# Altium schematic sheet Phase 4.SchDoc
size Tabloid; SheetNumber: 6; SheetTotal: 7
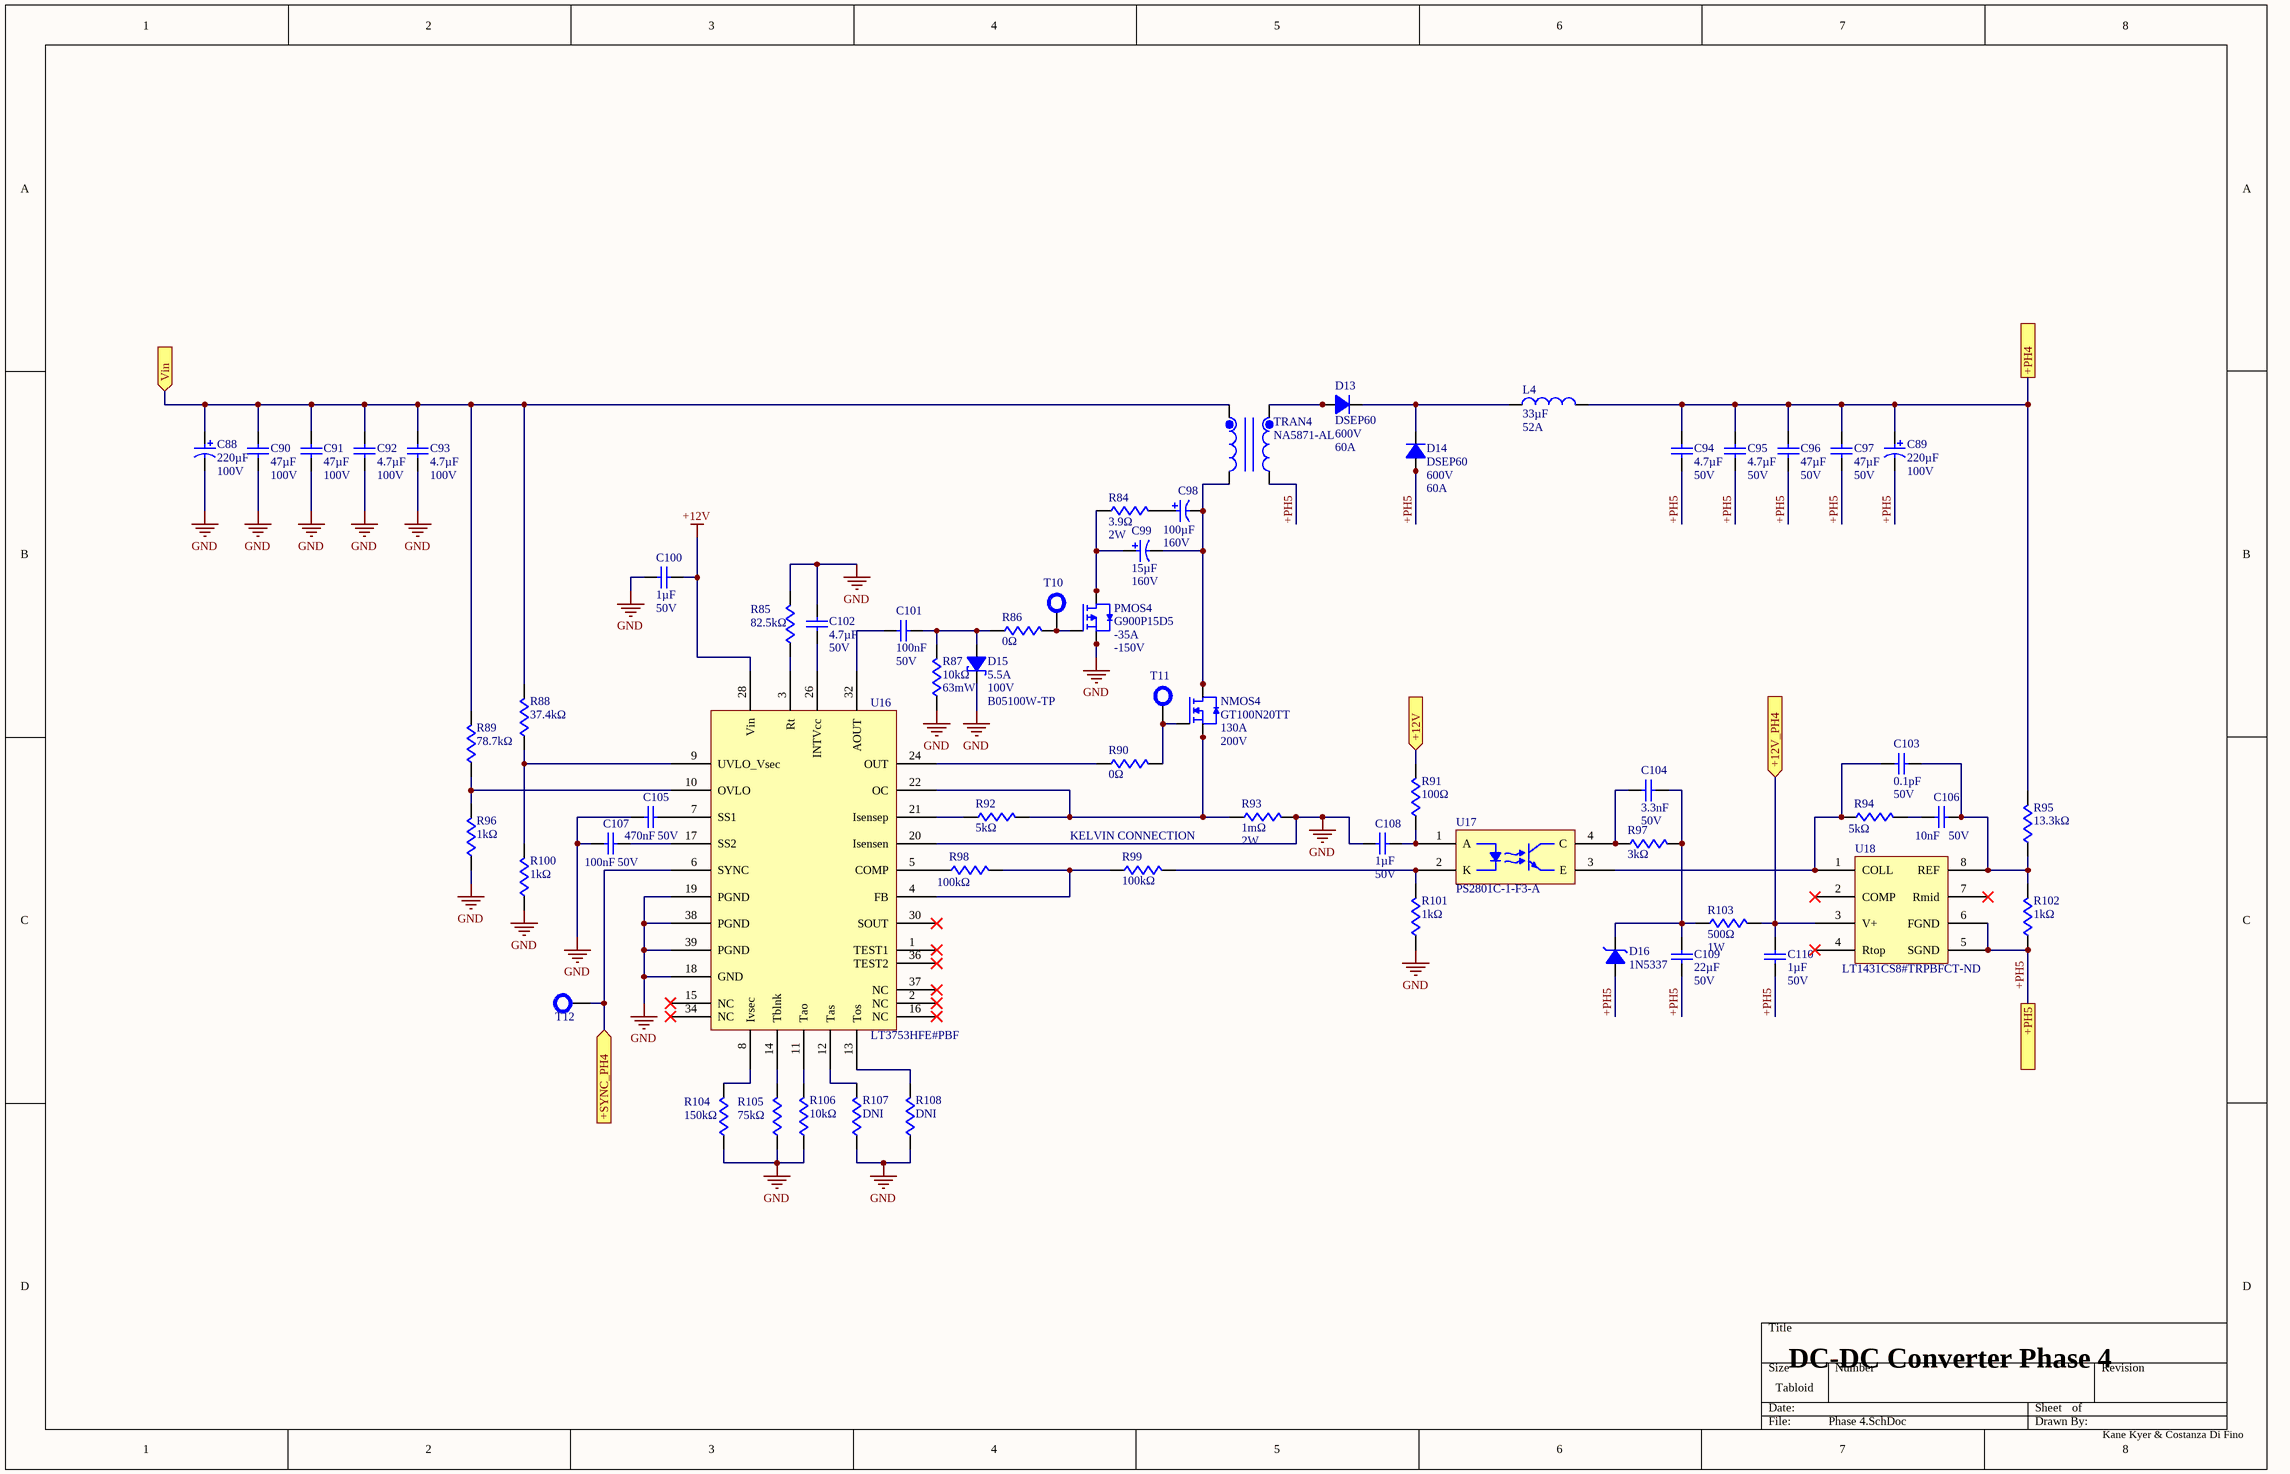
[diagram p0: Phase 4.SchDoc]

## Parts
C88  value 220µF  Voltage Rating: 100V  [C_AEC]  (hidden comment: AFK227M2AR44T-F)
C89  value 220µF  Voltage Rating: 100V  [C_AEC]  (hidden comment: AFK227M2AR44T-F)
C90  value 47µF  Voltage Rating: 100V  [C_CAA573]  (hidden comment: CAA573X7S2A476M640LH)
C91  value 47µF  Voltage Rating: 100V  [C_CAA573]  (hidden comment: CAA573X7S2A476M640LH)
C92  value 4.7µF  Voltage Rating (DC): 100V  [C_1210]  (hidden comment: GMC32X7S475K100NT)
C93  value 4.7µF  Voltage Rating (DC): 100V  [C_1210]  (hidden comment: GMC32X7S475K100NT)
C94  value 4.7µF  Voltage Rating (DC): 50V  [C_1206]  (hidden comment: GMC31X7R475K50NT)
C95  value 4.7µF  Voltage Rating (DC): 50V  [C_1206]  (hidden comment: GMC31X7R475K50NT)
C96  value 47µF  Voltage Rating (DC): 50V  [C_CKG57N]  (hidden comment: CKG57NX7R1H476M500JJ)
C97  value 47µF  Voltage Rating (DC): 50V  [C_CKG57N]  (hidden comment: CKG57NX7R1H476M500JJ)
C98  value 100µF  Voltage Rating (DC): 160V  [UUJ2C101MNJ1MS]  (hidden comment: UUJ2C101MNJ1MS)
C99  value 15µF  Voltage: 160V  [ULT2C150MNL1GS]  (hidden comment: ULT2C150MNL1GS)
C100  value 1µF  Voltage: 50V  [C_0805]  (hidden comment: CL21B105KBFNNNE)
C101  value 100nF  Voltage Rating: 50V  [C_0603]  (hidden comment: C0603C104K5RACTU)
C102  value 4.7µF  Voltage Rating (DC): 50V  [C_1206]  (hidden comment: GMC31X7R475K50NT)
C103  value 0.1pF  Voltage Rating: 50V  [C_0402]  (hidden comment: GJM1555C1HR10WB01D)
C104  value 3.3nF  Voltage Rating: 50V  [C_0603]  (hidden comment: GCM1885C1H332FA16D)
C105  value 470nF  Voltage Rating: 50V  [C_0402]  (hidden comment: GRM155R61H474KE11D)
C106  value 10nF  Voltage Rating: 50V  [C_0603]  (hidden comment: C0603C103K5RACTU)
C107  value 100nF  Voltage Rating: 50V  [C_0603]  (hidden comment: C0603C104K5RACTU)
C108  value 1µF  Voltage: 50V  [C_0805]  (hidden comment: CL21B105KBFNNNE)
C109  value 22µF  Voltage Rating (DC): 50V  [C_2220]  (hidden comment: GMC55X7R226M50NT)
C110  value 1µF  Voltage: 50V  [C_0805]  (hidden comment: CL21B105KBFNNNE)
D13  DSEP60  Vr: 600V  Io: 60A  [D_DSEP60]
D14  DSEP60  Vr: 600V  Io: 60A  [D_DSEP60]
D15  Max Forward Surge Current (Ifsm): 5.5A  Min Breakdown Voltage: 100V  [D_B05100W]  (hidden comment: B05100W-TP)
D16  Supplier Part Number: 1N5337  [D_1N5337]  (hidden comment: 1N5337BRLG)
L4  value 33µF  Irms: 52A  [CPEX4141L-330MC]  (hidden comment: CPEX4141L-330MC)
NMOS4  Id: 130A  Vds: 200V  [GT100N20TT]  (hidden comment: GT100N20TT)
PMOS4  Id: -35A  Vds: -150V  [G900P15]  (hidden comment: G900P15D5)
R84  value 3.9Ω  Power Rating: 2W  [R_SM2W]  (hidden comment: SMW23R9JT)
R85  value 82.5kΩ  [R_0805]  (hidden comment: RMCF0805FT82K5)
R86  value 0Ω  [R_0805]  (hidden comment: CRCW08050000Z0EA)
R87  value 10kΩ  Power Rating: 63mW  [R_0402]  (hidden comment: RM04F1002CT)
R88  value 37.4kΩ  [R_0603]  (hidden comment: RC0603FR-0737K4L)
R89  value 78.7kΩ  [R_0603]  (hidden comment: RC0603FR-0778K7L)
R90  value 0Ω  [R_0805]  (hidden comment: CRCW08050000Z0EA)
R91  value 100Ω  [R_0603]  (hidden comment: RC0603FR-07100RL)
R92  value 5kΩ  [R_0402]  (hidden comment: PNM0402E5001BST1)
R93  value 1mΩ  Power Rating: 2W  [R_2512]  (hidden comment: CRE2512-FZ-R001E-2)
R94  value 5kΩ  [R_0402]  (hidden comment: PNM0402E5001BST1)
R95  value 13.3kΩ  [R_0603]  (hidden comment: RMCF0603FT13K3)
R96  value 1kΩ  [R_0402]  (hidden comment: RM04F1001CT)
R97  value 3kΩ  [C_0402]  (hidden comment: AC0402FR-073KL)
R98  value 100kΩ  [R_0402]  (hidden comment: RM04F1003CT)
R99  value 100kΩ  [R_0402]  (hidden comment: RM04F1003CT)
R100  value 1kΩ  [R_0402]  (hidden comment: RM04F1001CT)
R101  value 1kΩ  [R_0402]  (hidden comment: RM04F1001CT)
R102  value 1kΩ  [R_0402]  (hidden comment: RM04F1001CT)
R103  value 500Ω  Power Rating: 1W  [R_WSC2515]  (hidden comment: WSC2515500R0FEB)
R104  value 150kΩ  [R_0603]  (hidden comment: RC0603FR-07150KL)
R105  value 75kΩ  [R_0603]  (hidden comment: AC0603FR-0775KL)
R106  value 10kΩ  [R_0402]  (hidden comment: RM04F1002CT)
R107  value DNI  [R_0805]  (hidden comment: CRCW08050000Z0EA)
R108  value DNI  [R_0805]  (hidden comment: CRCW08050000Z0EA)
T10  TEST  [TEST_POINT]  (value not drawn)
T11  TEST  [TEST_POINT]  (value not drawn)
T12  TEST  [TEST_POINT]  (value not drawn)
TRAN4  NA5871-AL  [NA5871-AL]
U16  LT3753HFE#PBF  [LT3753]
U17  PS2801C-1-F3-A  [PS2801C]
U18  Supplier Part Number: LT1431CS8#TRPBFCT-ND  [LT1431]  (hidden comment: LT1431CS8#TRPBF)

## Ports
+12V (in, see SHEET_MAP[4C], Externals[2A], Phase 1[4C], Phase 2[4C], Phase 3[4C], Phase 5[4B]), +12V_PH4 (in, see SHEET_MAP[4C], Externals[6B]), +PH4 (see SHEET_MAP[4C], Externals[6B], Phase 3[6C]), +PH5 (see SHEET_MAP[4C], Externals[6C], Phase 5[6B]), +SYNC_PH4 (in, see SHEET_MAP[4C], Externals[3C]), Vin (in, see SHEET_MAP[4C], Externals[1A], Phase 1[1B], Phase 2[1B], Phase 3[1B], Phase 5[1B])

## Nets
+12V: C100.2 U16.28(Vin)
GND: C88.2 C90.1 C91.1 C92.1 C93.1 C100.1 C102.1 C105.1 C107.1 C108.1 D15.1 PMOS4.1(S) PMOS4.2(S) PMOS4.3(S) R85.2 R87.1 R93.2 R96.1 R100.1 R101.1 R104.1 R105.1 R106.1 R107.1 R108.1 U16.18(GND) U16.19(PGND) U16.20(Isensen) U16.38(PGND) U16.39(PGND)
+12V: R91.2 ; port +12V  [a separate net that carries the same name]
+12V_PH4: C110.2 R103.2 U18.3(V+) ; port +12V_PH4
+PH4: C89.1 C94.2 C95.2 C96.2 C97.2 L4.2 R95.2 ; port +PH4
+PH5: C89.2 C94.1 C95.1 C96.1 C97.1 C109.1 C110.1 D14.1(A) D14.3(A) D16.2 R102.1 TRAN4.11 U18.5(SGND) U18.6(FGND) ; port +PH5
+SYNC_PH4: T12.1 U16.6(SYNC) ; port +SYNC_PH4
Vin: C88.1 C90.2 C91.2 C92.2 C93.2 R88.2 R89.2 TRAN4.1 ; port Vin
NetC98_1: C98.1 R84.2
NetC98_2: C98.2 C99.2 NMOS4.9(D) NMOS4.10(D) NMOS4.11(D) NMOS4.12(D) NMOS4.13(D) NMOS4.14(D) NMOS4.15(D) NMOS4.16(D) TRAN4.4
NetC99_1: C99.1 PMOS4.5(D) PMOS4.6(D) PMOS4.7(D) PMOS4.8(D) R84.1
NetC101_1: C101.1 U16.32(AOUT)
NetC101_2: C101.2 D15.2 R86.1 R87.2
NetC102_2: C102.2 U16.26(INTVcc)
NetC103_1: C103.1 R94.1 U17.3(E) U18.1(COLL)
NetC103_2: C103.2 C106.2 R95.1 R102.2 U18.8(REF)
NetC104_1: C104.1 R97.1 U17.4(C)
NetC104_2: C104.2 C109.2 D16.1 R97.2 R103.1
NetC105_2: C105.2 U16.7(SS1)
NetC106_1: C106.1 R94.2
NetC107_2: C107.2 U16.17(SS2)
NetC108_2: C108.2 R91.1 U17.1(A)
NetD13_1: D13.1(A) D13.3(A) TRAN4.6
NetD13_4: D13.4(C) D14.4(C) L4.1
NetNMOS4_1: NMOS4.1(S) NMOS4.2(S) NMOS4.3(S) NMOS4.4(S) NMOS4.5(S) NMOS4.6(S) NMOS4.7(S) R92.2 R93.1 U16.22(OC)
NetNMOS4_8: NMOS4.8(G) R90.2 T11.1
NetPMOS4_4: PMOS4.4(G) R86.2 T10.1
NetR85_1: R85.1 U16.3(Rt)
NetR88_1: R88.1 R100.2 U16.9(UVLO_Vsec)
NetR89_1: R89.1 R96.2 U16.10(OVLO)
NetR90_1: R90.1 U16.24(OUT)
NetR92_1: R92.1 U16.21(Isensep)
NetR98_1: R98.1 U16.5(COMP)
NetR98_2: R98.2 R99.1 U16.4(FB)
NetR99_2: R99.2 R101.2 U17.2(K)
NetR104_2: R104.2 U16.8(Ivsec)
NetR105_2: R105.2 U16.14(Tblnk)
NetR106_2: R106.2 U16.11(Tao)
NetR107_2: R107.2 U16.12(Tas)
NetR108_2: R108.2 U16.13(Tos)

Not connected (* = marked no-connect by the designer): U16 1(TEST1)* 2(NC)* 15(NC)* 16(NC)* 30(SOUT)* 34(NC)* 36(TEST2)* 37(NC)*; U18 2(COMP)* 4(Rtop)* 7(Rmid)*

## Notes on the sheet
- (near R99) KELVIN CONNECTION
- DC-DC Converter Phase 4
- Kane Kyer & Costanza Di Fino

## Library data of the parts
C88 C89 = AFK227M2AR44T-F: Radial Can - SMD ALUMINUM ELECTROLYTIC CAPACITOR AFK 100V 220muF ±20% 0.709Dia 18.00mm; Manufacturer: Cornell Dubilier; Dissipation Factor: 0.07%; ESR (Equivalent Series Resistance): 150mΩ; Leakage Current: 220µA; Life (Hours): 5000hours; Ripple Current: 687.75mA; Ripple Current (AC): 917mA
C90 C91 = CAA573X7S2A476M640LH: Multilayer Ceramic Chip Capacitors, Capacitance=47μF, LxWxT: 6.0x7.5x6.4mm; Manufacturer: TDK; Manufacturer Lifecycle Status: PRODUCTION; Tolerance: 20%
C92 C93 = GMC32X7S475K100NT: Ceramic Capacitor, Multilayer, Ceramic, 100V, 10% +Tol, 10% -Tol, X7S, 22% TC, 4.7uF, Surface Mount, 1210; Manufacturer: Cal-Chip Electronics
C94 C95 C102 = GMC31X7R475K50NT: Ceramic Capacitor, Multilayer, Ceramic, 50V, 10% +Tol, 10% -Tol, X7R, 15% TC, 4.7uF, Surface Mount, 1206; Manufacturer: Cal-Chip Electronics
C96 C97 = CKG57NX7R1H476M500JJ: Ceramic Capacitor, Multilayer, Ceramic, 50V, 20% +Tol, 20% -Tol, X7R, 15% TC, 47uF, Surface Mount, 2420; Manufacturer: TDK; Manufacturer Lifecycle Status: PRODUCTION
C98 = UUJ2C101MNJ1MS: Aluminum Electrolytic Capacitors 100 F 160 V Radial, SMD 5000 Hrs 105C; Manufacturer: Nichicon; Leakage Current: 740µA; Ripple Current: 380mA
C99 = ULT2C150MNL1GS: Radial Can - SMD ALUMINUM ELECTROLYTIC CAPACITOR ULT 160V 15muF ±20% 0.315Dia 8.00mm; Manufacturer: Nichicon; Leakage Current: 196µA; Life (Hours): 2000hours; Polarity: Polar; Ripple Current: 45mA
C100 C108 C110 = CL21B105KBFNNNE: 50V 1uF X7R ±10% 0805 Multilayer Ceramic Capacitors MLCC - SMD/SMT ROHS; Manufacturer: Samsung Electro-Mechanics
C101 C107 = C0603C104K5RACTU: 50V 100nF X7R ±10% 0603 Multilayer Ceramic Capacitors MLCC - SMD/SMT ROHS; Manufacturer: KEMET; Dissipation Factor: 2.5%; Temperature Coefficient: 30ppm/°C
C103 = GJM1555C1HR10WB01D: Multilayer Ceramic Capacitor, 0.1 pF, 50 V, ± 0.05pF, C0G (NP0), 0402 [1005 Metric]; Manufacturer: Murata; Manufacturer Lifecycle Status: IN PRODUCTION; Temperature Coefficient: 30ppm/°C
C104 = GCM1885C1H332FA16D: 50V 3.3nF C0G ±1% 0603 Multilayer Ceramic Capacitors MLCC - SMD/SMT ROHS; Manufacturer: Murata; Manufacturer Lifecycle Status: IN PRODUCTION; Temperature Coefficient: 30ppm/°C
C105 = GRM155R61H474KE11D: 50V 470nF X5R ±10% 0402 Multilayer Ceramic Capacitors MLCC - SMD/SMT ROHS; Manufacturer: Murata; Manufacturer Lifecycle Status: IN PRODUCTION
C106 = C0603C103K5RACTU: Capacitor, Multilayer, Ceramic, 50V, 10%, X7R, 15% Tc, 0.01Uf, Surface Mount, 0603; Manufacturer: KEMET; Dissipation Factor: 2.5%; Temperature Coefficient: 30ppm/°C
C109 = GMC55X7R226M50NT: Ceramic Capacitor, Multilayer, Ceramic, 50V, 20% +Tol, 20% -Tol, X7R, 15% TC, 22uF, Surface Mount, 2220; Manufacturer: Cal-Chip Electronics
D13 D14 = DSEP60-06AZ-TRL: Power Diode Discretes-FRED TO-; Manufacturer: IXYS
D15 = B05100W-TP: Rectifier Diode, Schottky, 1 Phase, 1 Element, 0.5A, 100V V(RRM), Silicon; Manufacturer: MCC; Forward Voltage: 850mV; Max Output current: 500mA; Number of Elements: 1; Peak Reverse Current: 1µA
D16 = 1N5337BRLG: Zener Diode Single 4.7V 5% 2Ohm 5000mW 2-Pin Case 017AA-01 T/R / DIODE ZENER 4.7V 5W AXIAL; Manufacturer: onsemi; Manufacturer Lifecycle Status: ACTIVE; Forward Voltage: 1.2V; Impedance: 2Ω; Max Reverse Leakage Current: 5µA; Number of Elements: 1; Polarity: Unidirectional; Test Current: 260mA
L4 = CPEX4141L-330MC: Fixed Ind 33UH 52A 1.88 Mohm Th; Manufacturer: Codaca
NMOS4 = GT100N20TT: Mosfet N-ch 200V 130A 280W Tolt; Manufacturer: GoFord
PMOS4 = G900P15D5: P-150V, -60A, RD(max) Less Than 80mOhm at -10V, VTH -1V to -4V, DFN5x6-8L; Manufacturer: GoFord; Manufacturer Lifecycle Status: ACTIVE
R84 = SMW23R9JT: SM Series 3.9 Ohm ±5 % 2 W ±200 ppm/°C Surface Mount Wirewound Resistor; Manufacturer: TE Connectivity; Manufacturer Lifecycle Status: ACTIVE; Insulation Resistance: 10GΩ; Number of Resistors: 1; Operating Supply Voltage: 300V; Tolerance: 5%
R85 = RMCF0805FT82K5: Res Thick Film 0805 82.5K Ohm 1% 1/8W ±100ppm/°C Molded SMD SMD Paper T/R; Manufacturer: Stackpole Electronics; Max Power Dissipation: 125mW; Voltage Rating: 150V
R86 R90 R107 R108 = CRCW08050000Z0EA: Zero Ohm Resistor, Jumper, 0805 [2012 Metric], Thick Film, 125 mW, 2.5 A, Surface Mount Device; Manufacturer: Vishay; Manufacturer Package Identifier: CRCW0805-e3; Power Dissipation: 125mW; Temperature Coefficient: 100ppm/°C; Tolerance: 1%; Voltage Rating: 150V
R87 = RM04F1002CT: Fixed Resistor, Metal Glaze/thick Film, 0.0625W, 10000ohm, 50V, 1% +/-Tol, Surface Mount, 0402; Manufacturer: Cal-Chip Electronics; Power Dissipation: 62.5mW; Temperature Coefficient: 100ppm/°C
R88 = RC0603FR-0737K4L: 100mW Thick Film Resistors 75V ±100ppm/℃ ±1% 37.4kΩ 0603 Chip Resistor - Surface Mount ROHS; Manufacturer: Yageo Group; Temperature Coefficient: 100ppm/°C; Voltage Rating (DC): 50V
R89 = RC0603FR-0778K7L: Res Thick Film 0603 78.7K Ohm 1% 0.1W(1/10W) ±100ppm/C Pad SMD T/R; Manufacturer: Yageo Group; Power Dissipation: 100mW; Temperature Coefficient: 100ppm/°C; Voltage Rating: 75V; Voltage Rating (DC): 50V
R91 = RC0603FR-07100RL: Yageo RC0603FR-07100RL 0603 SMD Resistor 100 Ohm thin film chip resistor; Manufacturer: Yageo Group; Power Dissipation: 100mW; Temperature Coefficient: 100ppm/°C; Tolerance: 1%; Voltage Rating: 75V; Voltage Rating (DC): 50V
R92 R94 = PNM0402E5001BST1: Res Thin Film 0402 5K Ohm 0.1% 0.05W(1/20W) +/-25ppm/C Sulfur Resistant Pad SMD Medical T/R; Manufacturer: Vishay; Power Dissipation: 50mW; Temperature Coefficient: 25ppm/°C; Working Voltage: 75V
R93 = CRE2512-FZ-R001E-2: Res Thick Film 2512 1m Ohm 1% 2W ±75ppm/°C Molded SMD Embossed T/R; Manufacturer: Bourns; Temperature Coefficient: 50ppm/°C
R95 = RMCF0603FT13K3: Res Thick Film 0603 13.3K Ohm 1% 0.1W(1/10W) ±100ppm/C Pad SMD Automotive T/R; Manufacturer: Stackpole Electronics; Power Dissipation: 100mW; Temperature Coefficient: 100ppm/°C; Voltage Rating: 75V
R96 R100-R102 = RM04F1001CT: 62.5mW Thick Film Resistors ±100ppm/℃ ±1% 1kΩ 0402 Chip Resistor - Surface Mount ROHS; Manufacturer: Cal-Chip Electronics; Temperature Coefficient: 100ppm/°C; Working Voltage: 50V
R97 = AC0402FR-073KL: Res Thick Film 0402 3K Ohm 1% 0.063W(1/16W) ±100ppm/C Pad SMD Automotive T/R; Manufacturer: Yageo Group; Max Power Dissipation: 63mW; Power Dissipation: 62.5mW; Temperature Coefficient: 100ppm/°C; Voltage Rating: 50V
R98 R99 = RM04F1003CT: Fixed Resistor, Metal Glaze/thick Film, 0.0625W, 100000ohm, 50V, 1% +/-Tol, Surface Mount, 0402; Manufacturer: Cal-Chip Electronics; Power Dissipation: 62.5mW; Temperature Coefficient: 100ppm/°C
R103 = WSC2515500R0FEB: Fixed Resistor, Wire Wound, 1W, 500ohm, 22.3607V, 1% +/-Tol, 20ppm/Cel, Surface Mount, 2515; Manufacturer: Vishay; Temperature Coefficient: 20ppm/°C
R104 = RC0603FR-07150KL: 100mW Thick Film Resistors 75V ±100ppm/℃ ±1% 150kΩ 0603 Chip Resistor - Surface Mount ROHS; Manufacturer: Yageo Group; Temperature Coefficient: 100ppm/°C; Voltage Rating (AC): 50V
R105 = AC0603FR-0775KL: Res Thick Film 0603 75K Ohm 1% 0.1W(1/10W) ±100ppm/C Pad SMD T/R Automotive AEC-Q200; Manufacturer: Yageo Group; Max Power Dissipation: 100mW; Temperature Coefficient: 100ppm/°C; Voltage Rating: 75V
R106 = RM04F1002CT: Fixed Resistor, Metal Glaze/thick Film, 0.0625W, 10000ohm, 50V, 1% +/-Tol, Surface Mount, 0402; Manufacturer: Cal-Chip Electronics; Power Dissipation: 62.5mW; Power Rating: 63mW; Temperature Coefficient: 100ppm/°C
TRAN4 = NA5871-AL: Transformer, planar, for TI UCC28950, SMT, RoHS; Manufacturer: Coilcraft; Max Supply Voltage: 60V; Min Input Voltage: 38V; Power Rating: 800W
U16 = LT3753HFE#PBF: 500kHz 8.5V~100V Buck-boost type 1 TSSOP-38-EP-4.4mm DC-DC Controllers ROHS; Manufacturer: Analog Devices; Manufacturer Lifecycle Status: PRODUCTION; Clock Sync: Yes; Max Supply Voltage: 100V; Min Supply Voltage: 8.5V; Nominal Supply Voltage: 12V; Number of Output Phases: 1; Topology: Forward Converter
U17 = PS2801C-1-F3-A: Optocoupler DC-IN 1-CH Transistor DC-OUT 4-Pin SSOP T/R; Manufacturer: Renesas; Manufacturer Lifecycle Status: ACTIVE; Collector Emitter Breakdown Voltage: 80V; Collector Emitter Saturation Voltage: 300mV; Current Transfer Ratio: 50%; Dark Current: 100nA; Forward Current: 30mA; Forward Voltage: 1.4V; Input Current: 5mA; Isolation Voltage: 2.5kV; Max Power Dissipation: 120mW; Number of Elements: 1; Reverse Breakdown Voltage: 6V; Target Application: PLC\, Hybrid IC\, Power supply\, OA\, Measuring instrument\, Modem\, Communication devices
U18 = LT1431CS8#TRPBF: V-Ref Adjustable 2.5V to 36V 100mA 8-Pin SOIC N T/R; Manufacturer: Analog Devices; Manufacturer Lifecycle Status: PRODUCTION; Cathode Current: 1mA; Reference Type: Shunt; Temperature Coefficient: 30ppm/°C; Tolerance: 0.4%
